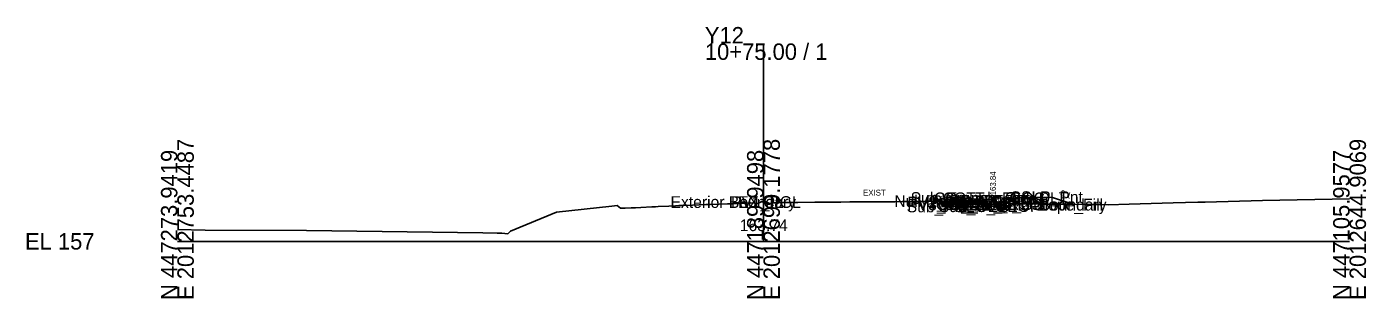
# Model space of a CAD drawing. Extents: x -26 to 1203, y -10 to 9542.
# Drawn here: x -25.7 to 202.8, y 1490.3 to 1536.6 of the extents above; entities that cross this region are included whole.
import ezdxf

# ---------------------------------------------------------------- set-up
doc = ezdxf.new("R2010")
doc.units = 0
for name, color, linetype in [('Default', 7, 'Continuous'), ('Exist Cross Section Cell', 7, 'Continuous'), ('Exist XS Center Line Elevation Label', 7, 'Continuous'), ('Exist XS Ground Line', 7, 'Continuous'), ('Prop CMT Conc Surface', 7, 'Continuous'), ('Prop CMT Concrete Structures', 7, 'Continuous'), ('Prop CMT Pvmt Course 1', 7, 'Continuous'), ('Prop CMT Pvmt Course 1 CG', 7, 'Continuous'), ('Prop CMT Pvmt Course 2', 7, 'Continuous'), ('Prop CMT Pvmt Course 3', 7, 'Continuous'), ('Prop CMT Pvmt Surface', 7, 'Continuous'), ('Prop CMT Slope Grass', 7, 'Continuous'), ('Prop CMT Subgrade Earthwork', 7, 'Continuous'), ('Prop XS Earthwork Shape', 7, 'Continuous'), ('Prop XS Hydro Elevations', 7, 'Continuous'), ('Prop XS SE Text', 7, 'Continuous'), ('Prop XS Side Slope Text', 7, 'Continuous'), ('Scratch_Level_0', 7, 'Continuous')]:
    doc.layers.add(name, color=color, linetype=linetype)

msp = doc.modelspace()

# ---------------------------------------------------------------- linework, layer by layer
at = {"layer": 'Exist Cross Section Cell'}
for p, q in [((100, 1500), (100, 1533.74)), ((0, 1500), (100, 1500)), ((100, 1500), (200, 1500))]:
    msp.add_line(p, q, dxfattribs=at)
at = {"layer": 'Exist XS Ground Line'}
msp.add_lwpolyline([(0, 1502), (4.73, 1501.92), (22.01, 1501.85), (52.11, 1501.45), (54.59, 1501.39), (55.36, 1501.38), (56.36, 1501.27), (56.86, 1501.76), (64.68, 1504.99), (74.13, 1505.99), (75.05, 1506.1), (75.6, 1505.65), (76.39, 1505.67), (77.45, 1505.7), (78.18, 1505.74), (79.06, 1505.78), (80.97, 1505.88), (81.6, 1505.91), (82.01, 1505.93), (83.88, 1506.01), (84.98, 1506.06), (85.58, 1506.09), (86.21, 1506.11), (87.87, 1506.18), (90.16, 1506.26), (90.91, 1506.28), (92.42, 1506.34), (93.89, 1506.39), (94.23, 1506.4), (94.75, 1506.42), (96.04, 1506.47), (96.88, 1506.51), (97.82, 1506.55), (99.01, 1506.44), (99.61, 1506.74), (100, 1506.74), (100.41, 1506.74), (101.01, 1506.44), (101.37, 1506.52), (102.87, 1506.6), (103.99, 1506.61), (105.84, 1506.63), (108.79, 1506.66), (110, 1506.68), (110.46, 1506.68), (111.79, 1506.69), (113.21, 1506.7), (114.75, 1506.71), (117.77, 1506.72), (119.12, 1506.74), (120.31, 1506.75), (120.9, 1506.75), (122.39, 1506.76), (123.66, 1506.77), (124.96, 1506.79), (126.99, 1506.81), (129.57, 1506.85), (130.64, 1506.87), (132.49, 1506.76), (133.49, 1507.15), (133.96, 1507.28), (134.31, 1507.37), (134.85, 1507.35), (135.19, 1507.33), (135.98, 1507.17), (136.91, 1507.04), (138.53, 1506.87), (140.01, 1506.67), (140.54, 1506.6), (142.31, 1506.4), (143.6, 1506.41), (145.55, 1506.38), (146.12, 1506.39), (147.66, 1506.38), (148.12, 1506.36), (148.72, 1506.33), (152.06, 1506.33), (156.03, 1506.3), (157.04, 1506.28), (158.83, 1506.25), (162.37, 1506.34), (169.93, 1506.59), (174.09, 1506.67), (175.36, 1506.7), (185.12, 1506.99), (200, 1507.23)], dxfattribs=at)
at = {"layer": 'Prop CMT Conc Surface'}
msp.add_lwpolyline([(137.15, 1506.9), (139.15, 1506.84), (139.15, 1507.34), (139.65, 1507.34)], dxfattribs=at)
at = {"layer": 'Prop CMT Concrete Structures'}
for points in [[(137.15, 1506.9), (139.15, 1506.84), (139.15, 1507.34), (139.65, 1507.34)], [(139.65, 1507.34), (139.65, 1506.34), (137.15, 1506.32)], [(137.15, 1506.32), (137.15, 1506.9)]]:
    msp.add_lwpolyline(points, dxfattribs=at)
at = {"layer": 'Prop CMT Pvmt Course 1'}
for points in [[(100, 1506.7), (100, 1506.7)], [(130.63, 1506.87), (137.15, 1506.9)], [(130.63, 1506.87), (130.63, 1506.87)], [(130.63, 1506.62), (130.63, 1506.87)], [(137.15, 1506.65), (130.63, 1506.62)], [(137.15, 1506.9), (137.15, 1506.65)]]:
    msp.add_lwpolyline(points, dxfattribs=at)
at = {"layer": 'Prop CMT Pvmt Course 1 CG'}
for points in [[(137.15, 1506.32), (140.15, 1506.34), (140.48, 1506.01)], [(137.15, 1505.99), (137.15, 1506.32)], [(140.48, 1506.01), (137.15, 1505.99)]]:
    msp.add_lwpolyline(points, dxfattribs=at)
at = {"layer": 'Prop CMT Pvmt Course 2'}
for points in [[(130.63, 1506.62), (137.15, 1506.65)], [(130.63, 1506.29), (130.63, 1506.62)], [(137.15, 1506.32), (130.63, 1506.29)], [(137.15, 1506.65), (137.15, 1506.32)]]:
    msp.add_lwpolyline(points, dxfattribs=at)
at = {"layer": 'Prop CMT Pvmt Course 3'}
for points in [[(130.63, 1506.29), (137.15, 1506.32)], [(130.63, 1505.95), (130.63, 1506.29)], [(137.15, 1506.32), (137.15, 1505.99)], [(137.15, 1505.99), (130.63, 1505.95)]]:
    msp.add_lwpolyline(points, dxfattribs=at)
at = {"layer": 'Prop CMT Pvmt Surface'}
msp.add_lwpolyline([(130.63, 1506.87), (137.15, 1506.9)], dxfattribs=at)
at = {"layer": 'Prop CMT Slope Grass'}
msp.add_lwpolyline([(139.65, 1507.34), (149.15, 1507.53), (152.76, 1506.32)], dxfattribs=at)
at = {"layer": 'Prop CMT Subgrade Earthwork'}
for points in [[(130.63, 1505.95), (130.62, 1506.87)], [(137.15, 1505.99), (140.48, 1506.01), (141.85, 1507.38)], [(130.63, 1505.95), (137.15, 1505.99)], [(137.15, 1505.99), (130.63, 1505.95)]]:
    msp.add_lwpolyline(points, dxfattribs=at)
at = {"layer": 'Prop XS Earthwork Shape'}
for points in [[(140.48, 1506.01), (141.02, 1506.54), (140.54, 1506.6), (140.01, 1506.67), (139.65, 1506.72), (139.65, 1506.34), (137.15, 1506.32), (137.15, 1506.9), (132.79, 1506.88), (132.49, 1506.76), (130.64, 1506.87), (130.62, 1506.87), (130.63, 1505.95), (137.15, 1505.99)], [(135.19, 1507.33), (135.98, 1507.17), (136.91, 1507.04), (138.53, 1506.87), (138.61, 1506.85), (137.15, 1506.9), (132.79, 1506.88), (133.49, 1507.15), (133.96, 1507.28), (134.31, 1507.37), (134.85, 1507.35)], [(139.65, 1506.34), (137.15, 1506.32), (137.15, 1506.9), (138.61, 1506.85), (139.65, 1506.72)], [(141.85, 1507.38), (149.15, 1507.53), (152.76, 1506.32), (152.06, 1506.33), (148.72, 1506.33), (148.12, 1506.36), (147.66, 1506.38), (146.12, 1506.39), (145.55, 1506.38), (143.6, 1506.41), (142.31, 1506.4), (141.02, 1506.54)]]:
    msp.add_lwpolyline(points, close=True, dxfattribs=at)

# ---------------------------------------------------------------- texts
at = {"layer": 'Default'}
msp.add_text('-', height=0.0001, dxfattribs=at).set_placement((0, 1500))
at = {"layer": 'Exist Cross Section Cell'}
for s, p in [('Y12', (90, 1533.74)), ('10+75.00 / 1', (90, 1530.94)), ('EL 157', (-26, 1498.6))]:
    msp.add_text(s, height=2.8, dxfattribs=at).set_placement(p)
for s, p in [('N 447273.9419', (0, 1490)), ('E 2012753.4487', (2.8, 1490)), ('N 447189.9498', (100, 1490)), ('E 2012699.1778', (102.8, 1490)), ('N 447105.9577', (200, 1490)), ('E 2012644.9069', (202.8, 1490))]:
    msp.add_text(s, height=2.8, rotation=90, dxfattribs=at).set_placement(p)
at = {"layer": 'Exist XS Center Line Elevation Label'}
msp.add_text('163.74', height=2, dxfattribs=at).set_placement((95.96, 1501.74))
at = {"layer": 'Prop XS Hydro Elevations'}
msp.add_text('163.84', height=1, rotation=90, dxfattribs=at).set_placement((139.65, 1507.84))
at = {"layer": 'Prop XS SE Text'}
msp.add_text('EXIST', height=1, rotation=0.3174, dxfattribs=at).set_placement((117, 1507.79))
at = {"layer": 'Prop XS Side Slope Text'}
msp.add_text('3:1', height=1, rotation=341.5651, dxfattribs=at).set_placement((150.55, 1507.85))
at = {"layer": 'Scratch_Level_0'}
for s, p in [('Sub_Trench_Out_DLT', (125.11, 1506.38)), ('CG_Top_Face', (129.1, 1506.34)), ('CG_Top_BOC', (130.62, 1506.34)), ('CSLP_Pnt', (142.01, 1506.53)), ('Exterior Boundary', (84.14, 1505.7)), ('PV1_PGL', (94.47, 1505.7)), ('EX CL', (95.67, 1505.7)), ('Null Ex EOP', (122.33, 1505.87)), ('Sub_PGL', (124.44, 1504.95)), ('PV2_PGL', (124.53, 1505.62)), ('PV3_PGL', (124.53, 1505.29)), ('PV1', (128.7, 1505.87)), ('CG1_Shelf_Out', (129.39, 1505.34)), ('CG_Bot_IE', (129.75, 1505.32)), ('Sub_OEOT', (129.92, 1504.99)), ('CG_Top_Gut', (130.08, 1505.84)), ('PV2_OEOT', (130.01, 1505.65)), ('PV3_OEOT', (130.01, 1505.32)), ('CG_Bot_BOC', (130.65, 1505.34)), ('PV1_OEOT', (130.58, 1505.9)), ('Sub_OEOP', (133.28, 1505.01)), ('Exterior Boundary', (137.13, 1505.25)), ('Slope_Fill', (146.2, 1505.25))]:
    msp.add_text(s, height=2, dxfattribs=at).set_placement(p)

doc.saveas('drawing.dxf')
